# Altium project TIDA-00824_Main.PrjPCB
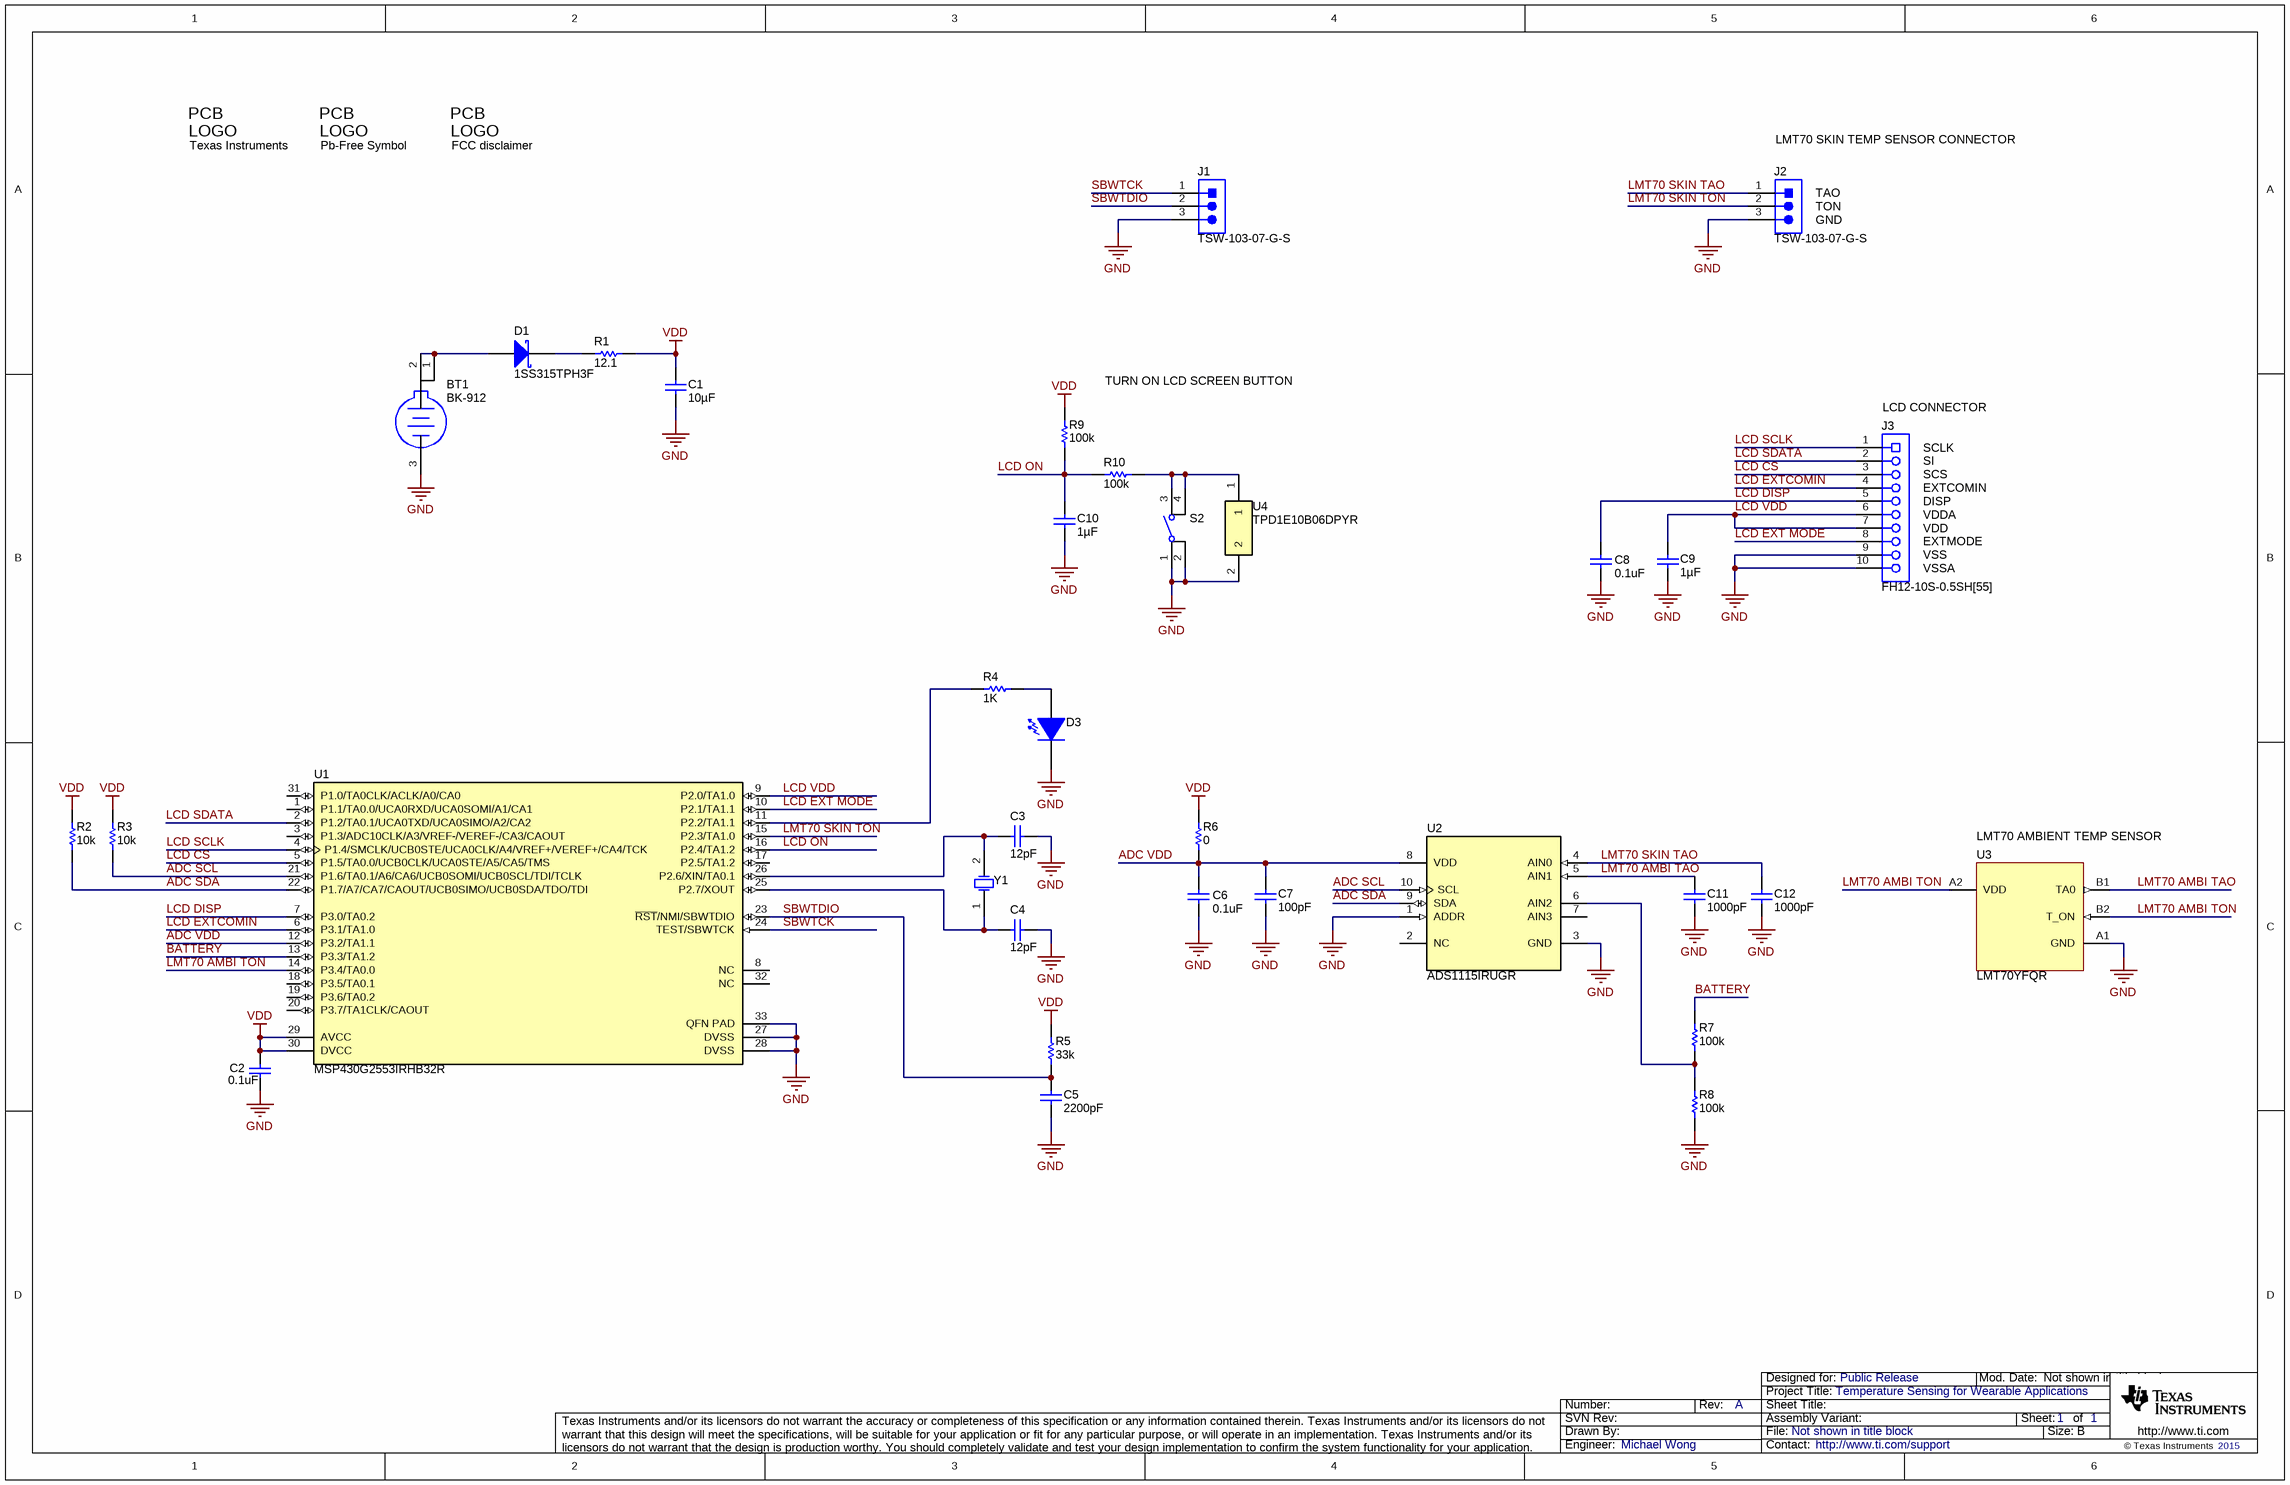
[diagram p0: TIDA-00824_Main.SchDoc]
TechSupport: http://www.ti.com/support; SCH_Rev: A; PRJ_Title: Temperature Sensing for Wearable Applications; PRJ_Engineer: Michael Wong; PRJ_Customer: Public Release; PCB_Rev: A; PCB_Layout: Michael Wong; CopyrightYear: 2015
1 sheet, 37 parts. Net scope: global (net labels, ports and power ports of the same name join across sheets).
Board file: TIDA-00824_Main.PcbDoc

## Sheet TIDA-00824_Main.SchDoc
size 431 x 279 mm; Date: Not shown in title block; ApprovedBy: Not shown in title block; CheckedBy: Not shown in title block; Author: Not shown in title block; CompanyName: Not shown in title block; Engineer: Not shown in title block; Organization: Not shown in title block; Address1: Not shown in title block; Address2: Not shown in title block; Address3: Not shown in title block; Address4: Not shown in title block; DocumentNumber: 1; Revision: Use project parameter SCH_Rev; SheetNumber: 1; SheetTotal: 1; PageSetup: Record=PageOptions¦CenterHorizontal=True¦CenterVertical=True¦PrintScale=1.00¦XCorrection=1.00¦YCorrection=1.00¦PrintKind=0¦BorderSize=5000000¦LeftOffset=0¦BottomOffset=0¦Orientation=2¦PaperLength=1000¦PaperWidth=1000¦Scale=100¦PaperSource=15¦PrintQuality=600¦MediaType=1¦DitherType=10¦PaperKind=Letter¦PrintScaleMode=1

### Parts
BT1  BK-912  [MPD_BK-912]
C1  ValueDisplayed: 10µF  [0603]  (hidden comment: C1608X5R1A106M)
C2  value 0.1uF  [0402]  (hidden comment: GRM155R71C104JA88D)
C3  ValueDisplayed: 12pF  [0402]  (hidden comment: GRM1555C1E120JA01D)
C4  ValueDisplayed: 12pF  [0402]  (hidden comment: GRM1555C1E120JA01D)
C5  ValueDisplayed: 2200pF  [0402]  (hidden comment: C1005X7R1H222K)
C6  value 0.1uF  [0402]  (hidden comment: GRM155R71C104JA88D)
C7  ValueDisplayed: 100pF  [0402]  (hidden comment: GRM1535C1H101JDD5D)
C8  value 0.1uF  [0402]  (hidden comment: GRM155R71C104JA88D)
C9  ValueDisplayed: 1µF  [0402]  (hidden comment: GRM155R6YA105KE11D)
C10  ValueDisplayed: 1µF  [0402]  (hidden comment: GRM155R6YA105KE11D)
C11  ValueDisplayed: 1000pF  [0402]  (hidden comment: GRM155R61E102KA01D)
C12  ValueDisplayed: 1000pF  [0402]  (hidden comment: GRM155R61E102KA01D)
D1  1SS315TPH3F  [sod-323]
D3  SML-LX0603SRW-TR  [0603]  (value not drawn)
J1  TSW-103-07-G-S  [TSW-103-07-G-S]
J2  TSW-103-07-G-S  [TSW-103-07-G-S]
J3  FH12-10S-0.5SH[55]  [Hirose_FH12-10S-0_5SH[55]]
Logo1  Texas Instruments  [TI_Stacked_Overlay_Small]  (no BOM)
Logo2  Pb-Free Symbol  [Pb-Free_Overlay_Medium]  (no BOM)
Logo3  FCC disclaimer  [FCC_disclaimer]  (no BOM)
R1  ValueDisplayed: 12.1  [0402]  (hidden comment: CRCW040212R1FKED)
R2  ValueDisplayed: 10k  [0402]  (hidden comment: CRCW040210K0JNED)
R3  ValueDisplayed: 10k  [0402]  (hidden comment: CRCW040210K0JNED)
R4  value 1K  [0402]  (hidden comment: ERJ-2GEJ102X)
R5  value 33k  [0402]  (hidden comment: CRCW040233K0JNED)
R6  ValueDisplayed: 0  [0402]  (hidden comment: CRCW04020000Z0ED)
R7  ValueDisplayed: 100k  [0402]  (hidden comment: CRCW0402100KFKED)
R8  ValueDisplayed: 100k  [0402]  (hidden comment: CRCW0402100KFKED)
R9  ValueDisplayed: 100k  [0402]  (hidden comment: CRCW0402100KFKED)
R10  ValueDisplayed: 100k  [0402]  (hidden comment: CRCW0402100KFKED)
S2  EVP-ANDA1A  [SW_EVPANDA]  (value not drawn)
U1  MSP430G2553IRHB32R  [RHB0032E]
U2  ADS1115IRUGR  [RUG0010A]
U3  LMT70YFQR  [YFQ0004ACAC]
U4  TPD1E10B06DPYR  [DPY0002A]
Y1  FC-12M 32.7680KA-A3  [Epson_FC-12M]  (value not drawn)

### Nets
GND: BT1.3(-) C1.2 C2.2 C3.1 C4.1 C5.2 C6.2 C7.2 C8.2 C9.2 C10.2 C11.2 C12.2 D3.2(K) J1.3 J2.3 J3.9 J3.10 R8.1 S2.1 S2.2 U1.27(DVSS) U1.28(DVSS) U1.33(QFN_PAD) U2.1(ADDR) U2.3(GND) U3.A1(GND) U4.2
VDD: C1.1 C2.1 R1.2 R2.2 R3.2 R5.1 R6.2 R9.1 U1.29(AVCC) U1.30(DVCC)
ADC SCL: R3.1 U1.21(P1.6/TA0.1/A6/CA6/UCB0SOMI/UCB0SCL/TDI/TCLK) U2.10(SCL)
ADC SDA: R2.1 U1.22(P1.7/A7/CA7/CAOUT/UCB0SIMO/UCB0SDA/TDO/TDI) U2.9(SDA)
ADC VDD: C6.1 C7.1 R6.1 U1.12(P3.2/TA1.1) U2.8(VDD)
BATTERY: R7.2 U1.13(P3.3/TA1.2)
LCD CS: J3.3 U1.5(P1.5/TA0.0/UCB0CLK/UCA0STE/A5/CA5/TMS)
LCD DISP: C8.1 J3.5 U1.7(P3.0/TA0.2)
LCD EXT MODE: J3.8 U1.10(P2.1/TA1.1)
LCD EXTCOMIN: J3.4 U1.6(P3.1/TA1.0)
LCD ON: C10.1 R9.2 R10.2 U1.16(P2.4/TA1.2)
LCD SCLK: J3.1 U1.4(P1.4/SMCLK/UCB0STE/UCA0CLK/A4/VREF+/VEREF+/CA4/TCK)
LCD SDATA: J3.2 U1.2(P1.2/TA0.1/UCA0TXD/UCA0SIMO/A2/CA2)
LCD VDD: C9.1 J3.6 J3.7 U1.9(P2.0/TA1.0)
LMT70 AMBI TAO: C11.1 U2.5(AIN1) U3.B1(TA0)
LMT70 AMBI TON: U1.14(P3.4/TA0.0) U3.A2(VDD) U3.B2(T_ON)
LMT70 SKIN TAO: C12.1 J2.1 U2.4(AIN0)
LMT70 SKIN TON: J2.2 U1.15(P2.3/TA1.0)
SBWTCK: J1.1 U1.24(TEST/SBWTCK)
SBWTDIO: C5.1 J1.2 R5.2 U1.23(~{RST}/NMI/SBWTDIO)
NetBT1_1: BT1.1(+) BT1.2(+) D1.2(A)
NetC3_2: C3.2 U1.26(P2.6/XIN/TA0.1) Y1.2(OSC2)
NetC4_2: C4.2 U1.25(P2.7/XOUT) Y1.1(OSC1)
NetD1_1: D1.1(K) R1.1
NetD3_1: D3.1(A) R4.2
NetR4_1: R4.1 U1.11(P2.2/TA1.1)
NetR7_1: R7.1 R8.2 U2.6(AIN2)
NetR10_1: R10.1 S2.3 S2.4 U4.1

Not connected (* = marked no-connect by the designer): U1 1(P1.1/TA0.0/UCA0RXD/UCA0SOMI/A1/CA1) 3(P1.3/ADC10CLK/A3/VREF-/VEREF-/CA3/CAOUT) 8(NC) 17(P2.5/TA1.2) 18(P3.5/TA0.1) 19(P3.6/TA0.2) 20(P3.7/TA1CLK/CAOUT) 31(P1.0/TA0CLK/ACLK/A0/CA0) 32(NC); U2 2(NC) 7(AIN3)

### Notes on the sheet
- (near J2) LMT70 SKIN TEMP SENSOR CONNECTOR
- (near J2) TON
- (near J2) TAO
- (near J2) GND
- (near R9) TURN ON LCD SCREEN BUTTON
- (near J3) LCD CONNECTOR
- (near J3) SCLK
- (near J3) SI
- (near J3) SCS
- (near J3) EXTCOMIN
- (near J3) DISP
- (near J3) VDDA
- (near J3) VDD
- (near J3) EXTMODE
- (near J3) VSS
- (near J3) VSSA
- (near U3) LMT70 AMBIENT TEMP SENSOR

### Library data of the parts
BT1 = BK-912: Battery Holder for CR2032, SMT; Manufacturer: Memory Protection Devices; SymbolCreator: Altium
C1 = C1608X5R1A106M: CAP, CERM, 10 µF, 10 V, +/- 20%, X5R, 0603; Manufacturer: TDK; Polarized: N; CompType: Capacitor; Value: 10uF; U/M: EA; Cap_F: 0.00001; Tolerance_%: 20; ESR_ohm: 0.0078; Value1: 0.0078 ohm; VDC_V: 10; Value2: 10V; IRMS_A: 1.85; TaMin_C: -55; TaMax_C: 85
C2 C6 C8 = 0402YC132KAT2A: CAP CER 0.1UF 16V 5% X7R 0402; Manufacturer: Murata Electronics North America; Polarized: N; CompType: Capacitor; U/M: EA; Cap_F: 0.0000000013; Tolerance_%: 10; VDC_V: 16; TaMin_C: -55; TaMax_C: 125
C3 C4 = GRM1555C1E120JA01D: CAP, CERM, 12 pF, 25 V, +/- 5%, C0G/NP0, 0402; Manufacturer: MuRata; Polarized: N; CompType: Capacitor; Value: 12pF; U/M: EA; Cap_F: 0.000000000012; Tolerance_%: 5; Value1: Unknown; VDC_V: 25; Value2: 25V; TaMin_C: -55; TaMax_C: 125
C5 = C1005X7R1H222K: CAP, CERM, 2200 pF, 50 V, +/- 10%, X7R, 0402; Manufacturer: TDK; Polarized: N; CompType: Capacitor; Value: 2200pF; U/M: EA; Cap_F: 0.0000000022; Tolerance_%: 10; ESR_ohm: 0.1433; Value1: 0.1433 ohm; VDC_V: 50; Value2: 50V; TaMin_C: -55; TaMax_C: 125
C7 = GRM1535C1H101JDD5D: CAP, CERM, 100 pF, 50 V, +/- 5%, C0G/NP0, 0402; Manufacturer: MuRata; Polarized: N; CompType: Capacitor; Value: 100pF; U/M: EA; Cap_F: 0.0000000001; Tolerance_%: 5; Value1: Unknown; VDC_V: 50; Value2: 50V; TaMin_C: -55; TaMax_C: 125
C9 C10 = GRM155R6YA105KE11D: CAP, CERM, 1 µF, 35 V, +/- 10%, X5R, 0402; Manufacturer: MuRata; Polarized: N; CompType: Capacitor; Value: 1uF; U/M: EA; Cap_F: 0.000001; Tolerance_%: 10; Value1: Unknown; VDC_V: 35; Value2: 35V; TaMin_C: -55; TaMax_C: 85
C11 C12 = GRM155R61E102KA01D: CAP, CERM, 1000 pF, 25 V, +/- 10%, X5R, 0402; Manufacturer: MuRata; Polarized: N; CompType: Capacitor; Value: 1000pF; U/M: EA; Cap_F: 0.000000001; Tolerance_%: 10; Value1: Unknown; VDC_V: 25; Value2: 25V; TaMin_C: -55; TaMax_C: 85; AEC Category: Q200
D1 = 1SS315TPH3F: Diode, Schottky, 5 V, 0.03 A, SOD-323; Manufacturer: Toshiba; U/M: EA; Vf_V: 0.38; Value: 5V; Value1: 0.03A; Value2: 0.38V; Io_A: 0.03; Vr_V: 5; TJmax_C: 125
D3 = LED: LED 660NM SUPER RED DIFF 0603SMD; Manufacturer: Lumex Opto/Components Inc; VendorPartNumber: 67-1551-1-ND; U/M: EA; Vendor: DigiKey
J1 J2 = TSW-103-07-G-S: Header, 100mil, 3x1, Gold, TH; Manufacturer: Samtec; SymbolCreator: a0799628; U/M: EA
J3 = FH12-10S-0.5SH[55]: Connector, FPC 10 Pos. 9.1x2.0x5.6 mm; Manufacturer: Hirose Electric Co. Ltd.; SymbolCreator: a0411947; U/M: EA
Logo1 = TI_Logo: Texas Instrument Corporate Signature; SymbolCreator: a0412235
Logo2 = Pb-Free: SymbolCreator: a0412235
Logo3 = FCC_disclaimer: SymbolCreator: codlsc
R1 = CRCW040212R1FKED: RES, 12.1, 1%, 0.063 W, 0402; Manufacturer: Vishay-Dale; CompType: Resistor; Value: 12.1; Value_Code: 12R1; Tolerance_%: 1; Power_W: 0.063; Value2: 0.063W; VDC_V: 50; TempCo: 100 ppm/C; EIA_Code: E96; U/M: EA
R2 R3 = CRCW040210K0JNED: RES, 10 k, 5%, 0.063 W, 0402; Manufacturer: Vishay-Dale; CompType: Resistor; Value: 10k; Res_ohm: 10000; Value_Code: 10k0; Tolerance_%: 5; Power_W: 0.063; Value2: 0.063W; VDC_V: 50; TempCo: 200 ppm/C; EIA_Code: E24; U/M: EA
R4 = CRCW040233R0JNED: RES 1K OHM 1/10W 5% 0402 SMD; Manufacturer: Panasonic Electronic Components; CompType: Resistor; Res_ohm: 33; Value_Code: 33R0; Tolerance_%: 5; Power_W: 0.063; Value2: 0.063W; VDC_V: 50; TempCo: 200 ppm/C; EIA_Code: E24; U/M: EA
R5 = CRCW040233K0JNED: RES, 33k ohm, 5%, 0.063W, 0402; Manufacturer: Vishay-Dale; CompType: Resistor; Res_ohm: 33000; Value_Code: 33k0; Tolerance_%: 5; Power_W: 0.063; VDC_V: 50; TempCo: 200 ppm/C; EIA_Code: E24; U/M: EA
R6 = CRCW04020000Z0ED: RES, 0, 5%, 0.063 W, 0402; Manufacturer: Vishay-Dale; CompType: Resistor; Value: 0; Value_Code: 0000; Tolerance_%: 5; Power_W: 0.063; Value2: 0.063W; VDC_V: 50; TempCo: 200 ppm/C; EIA_Code: E24; U/M: EA
R7-R10 = CRCW0402100KFKED: RES, 100 k, 1%, 0.063 W, 0402; Manufacturer: Vishay-Dale; CompType: Resistor; Value: 100k; Res_ohm: 100000; Tolerance_%: 1; Power_W: 0.063; Value2: 0.063W; VDC_V: 50; TempCo: 100 ppm/C; EIA_Code: E96; U/M: EA
S2 = EVP-ANDA1A: Switch, Slide, SPST-NO,  Off-Mom, 0.05 A,  12V, SMD; Manufacturer: Panasonic; SymbolCreator: a0412235; VDC_V: 12; PositionCount: 1; CurrentRating_mA: 50
U1 = MSP430G2553IRHB32R: 16 MHz Mixed Signal Microcontroller with 16 KB Flash, 512 B SRAM and 24 GPIOs, -40 to 85 degC, 32-pin QFN (RHB), Green (RoHS & no Sb/Br); Alternate Manufacturer: Texas Instruments; Alternate PartNumber: Equivalent; ADC: 10-bit SAR; ADC Channels: 8; Brown Out Reset: Yes; Flash(KB): 16; GPIO: 24; Pin/Package: 0DIESALE, 0WAFERSALE, 20PDIP, 20TSSOP, 28TSSOP, 32QFN; SRAM(B): 512; SubFamily: Value Line; Timers - 16-bit: 2; USCI_A (UART/LIN/IrDA/SPI): 1
U2 = ADS1115IRUGR: Ultra-Small, Low-Power, 16-Bit Analog-to-Digital Converter with Internal Reference, RUG0010A; Alternate PartNumber: ADS1115IRUGT; Manufacturer: Texas Instruments; SymbolCreator: Altium; CompType: IC; U/M: EA
U3 = LMT70YFQR: ±0.1°C Precision Analog Temperature Sensor, RTD and Precision NTC Thermistor IC, YFQ0004ACAC; Alternate PartNumber: LMT70YFQT; Manufacturer: Texas Instruments; SymbolCreator: a0411947; U/M: EA
U4 = TPD1E10B06DPYR: ESD in 0402 Package with 10 pF Capacitance and 6 V Breakdown, 1 Channel, -40 to +125 degC, 2-pin X2SON (DPY), Green (RoHS & no Sb/Br); Manufacturer: Texas Instruments; Alternate PartNumber: Equivalent; Breakdown Voltage(Min)(V): 6; Eco-Plan: TBD; IEC 61000-4-2 Air-Gap(+/- kV): 30; IO Capacitance(Typ)(pF): 10; SubFamily: ESD Solution
Y1 = FC-12M 32.7680KA-A3: Crystal, 32.768kHz, 12.5pF, SMD; Manufacturer: Epson; SymbolCreator: a0412235; U/M: EA; TaMin_C: -40; TaMax_C: 85; Frequency Stability: ±20ppm

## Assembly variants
001: not fitted J1 J2 R6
